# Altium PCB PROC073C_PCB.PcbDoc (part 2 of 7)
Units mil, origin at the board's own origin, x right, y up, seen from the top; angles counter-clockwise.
Board outline 2165.35 x 2695.12 mil, 8 copper layers (Top Layer, L2_GND, L3_SIGNAL 1, L4_SIGNAL 2, L5_SIGNAL 3, L6_SIGNAL 4, L7_GND, Bottom Layer), stack 55.9 mil thick; 393 components, 319 nets, 1311 pads, 1643 vias.
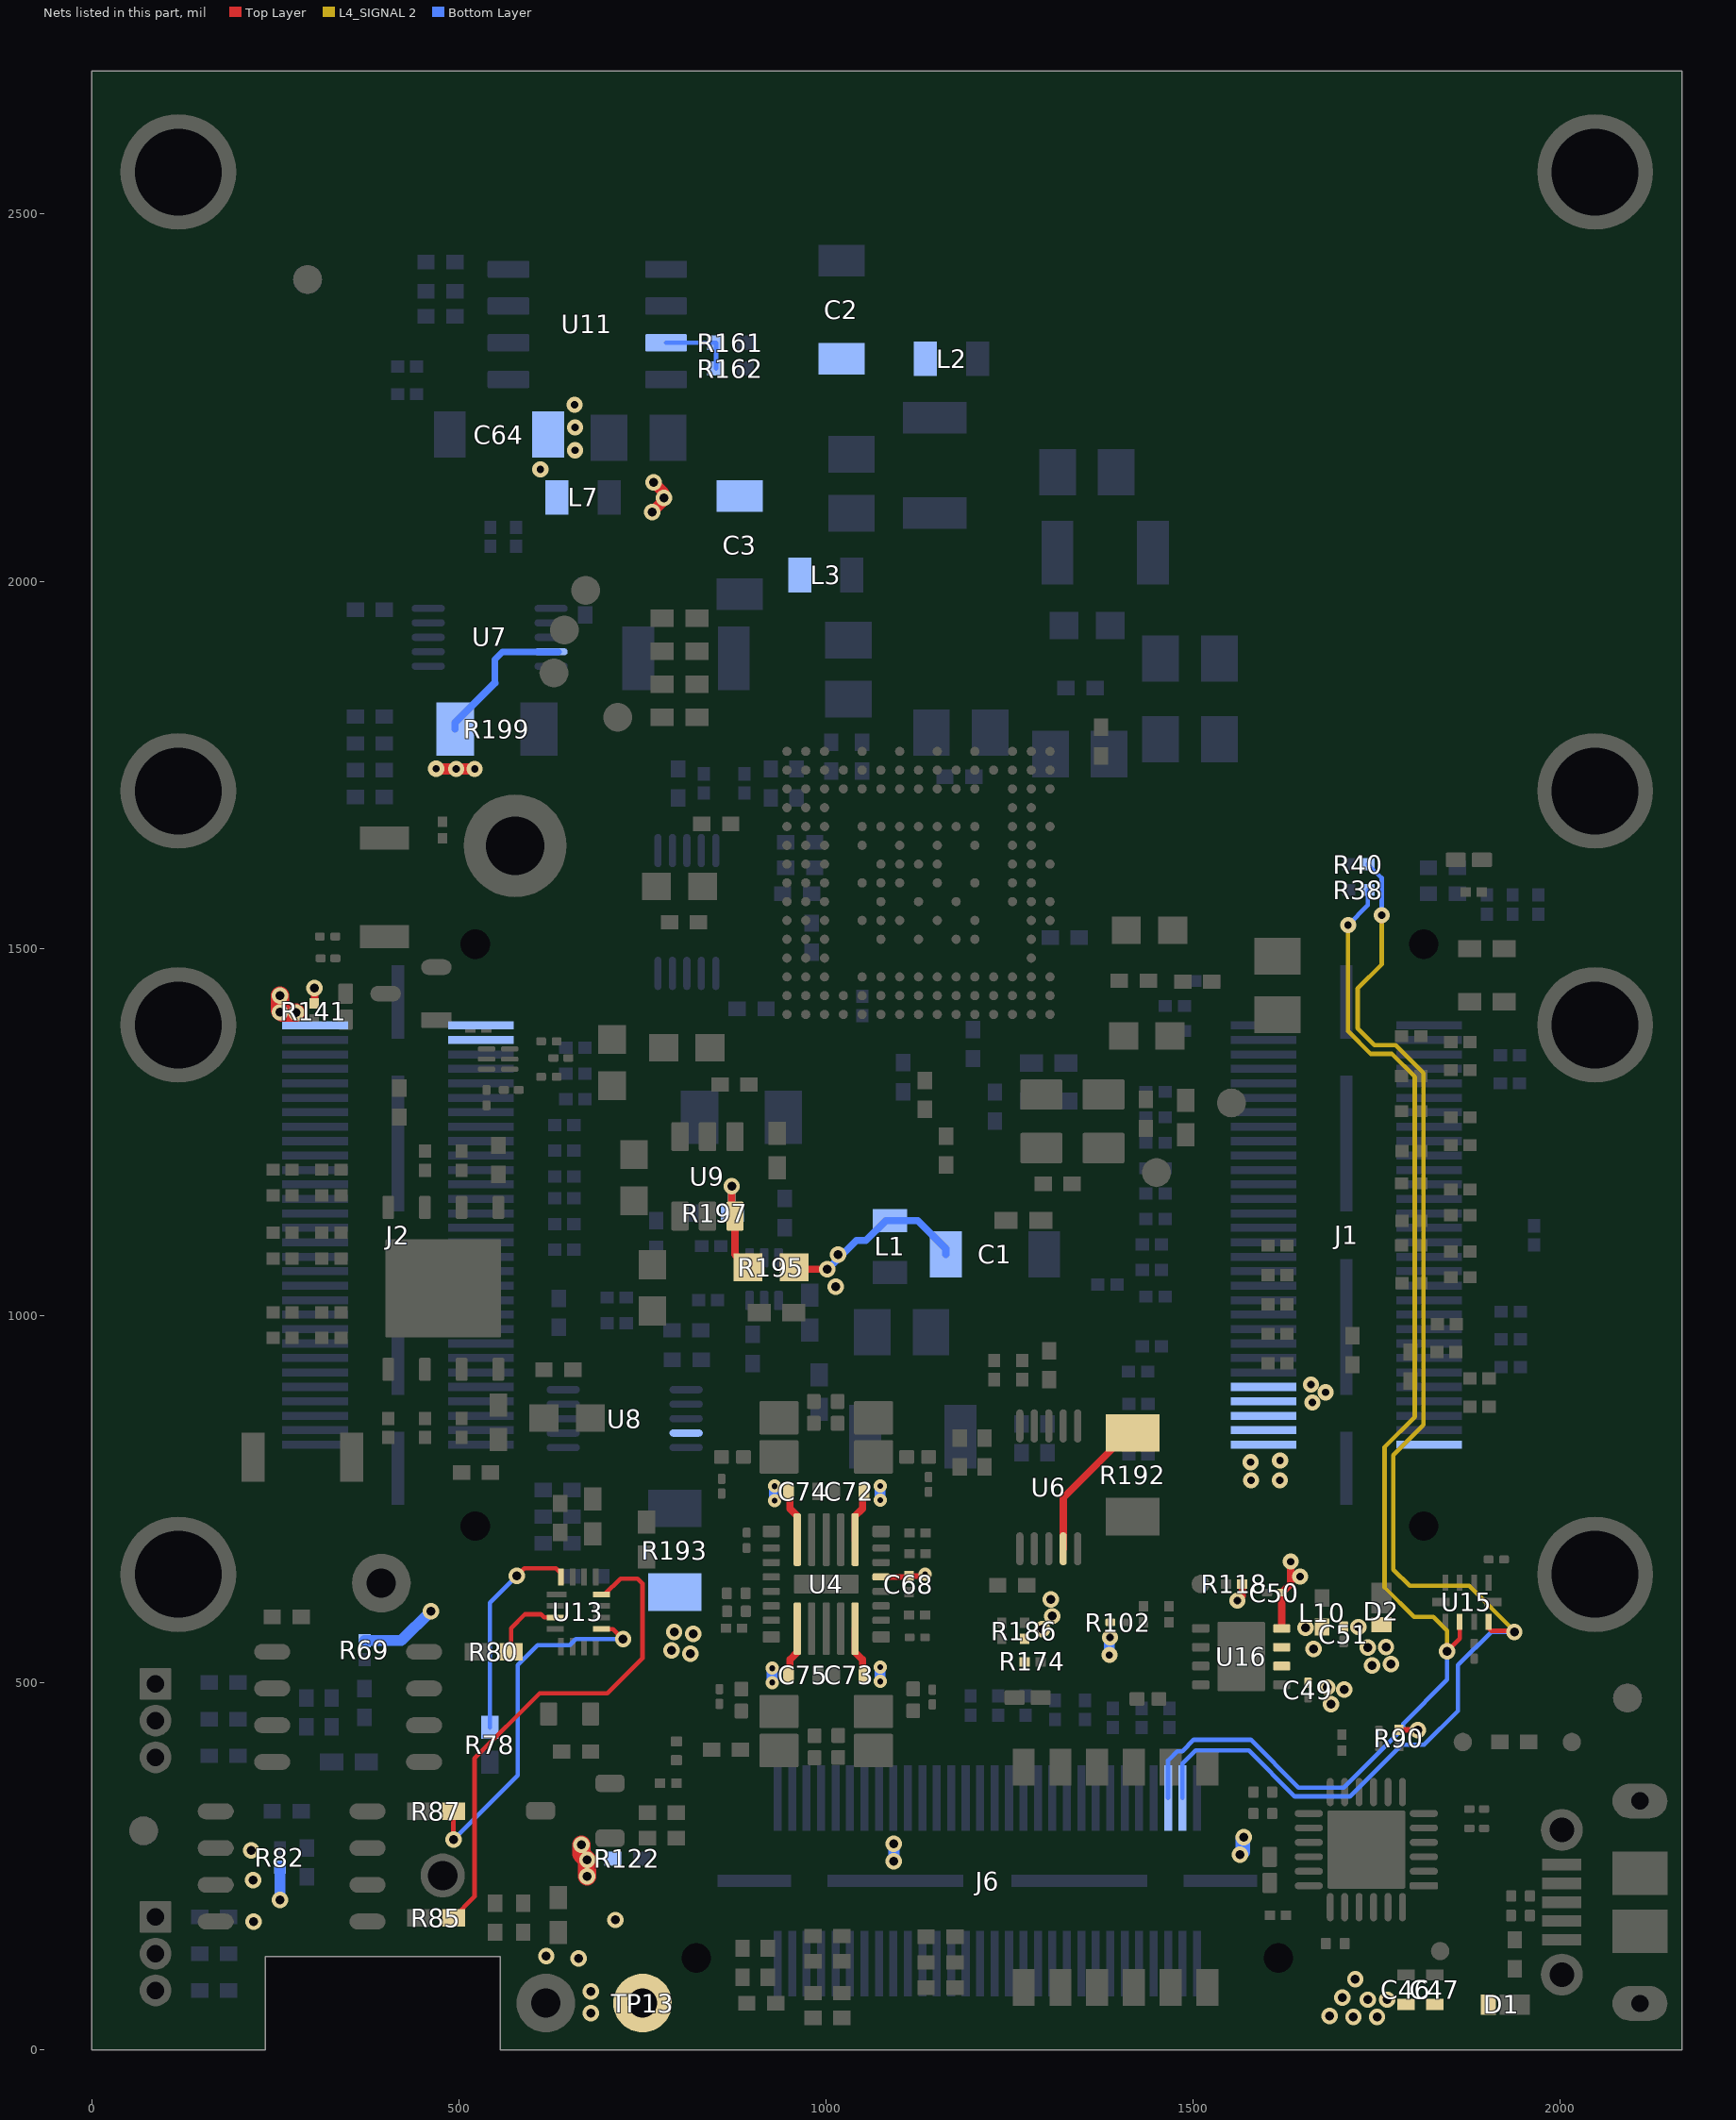
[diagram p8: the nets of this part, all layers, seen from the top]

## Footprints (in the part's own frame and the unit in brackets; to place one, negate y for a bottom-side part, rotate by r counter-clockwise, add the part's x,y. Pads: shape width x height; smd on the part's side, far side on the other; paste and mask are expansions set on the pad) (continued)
CONN_105017-0001 [mm] "Molex Micro USB-B"
  rect 0.4x1.35 smd: 1(-1.3,1.35) 2(-0.65,1.35) 3(0,1.35) 4(0.65,1.35) 5(1.3,1.35)
  oval 1.2x1.9 hole 0.6 slot 1.3 at 90 deg: 6(-3.5,-1.35) 9(3.5,-1.35)
  rect 1.5x1.9 smd: 7(-1,-1.35) 8(1,-1.35)
  round 1.45 hole 0.85: 10(2.5,1.35) 11(-2.5,1.35)
  Top Layer region: 3.5,-0.4 2.3,-0.4 2.3,-2.3 3.5,-2.3
  Top Layer region: -3.5,-2.3 -2.3,-2.3 -2.3,-0.4 -3.5,-0.4
  silkscreen extent -4.1,-0.2 4.1,1.4, body extent -4.1,-3.93 4.1,1.5, height 2.72
D0008A_L [mm] "SOIC, 8-Leads, Body 4.9x3.9mm, Pitch 1.27mm, IPC High Density"
  oval 1.25x0.55 smd: 1(-2.625,1.905) 2(-2.625,0.635) 3(-2.625,-0.635) 4(-2.625,-1.905) 5(2.625,-1.905) 6(2.625,-0.635) 7(2.625,0.635) 8(2.625,1.905)
  silkscreen extent -3.1,-2.5 0.9,2.5, body extent -3,-2.45 3,2.45, height 1.63
DBV0006A_N [mm] "SOT23, 6-Leads, Body 2.9x1.6mm, Pitch 0.95mm, Lead Span 2.8mm, IPC Medium Density"
  rrect17% 1x0.6 smd: 1(-1.375,0.95) 2(-1.375,0) 3(-1.375,-0.95) 4(1.375,-0.95) 5(1.375,0) 6(1.375,0.95)
  silkscreen extent -1.68,-1.55 0.5,1.55, body extent -1.42,-1.46 1.42,1.46, height 1.12
DGS0010A_L [mm] "TSSOP, 10-Leads, Body 3x3mm, Pitch 0.5mm, IPC High Density"
  oval 1.15x0.25 smd: 1(-2.125,1) 2(-2.125,0.5) 3(-2.125,0) 4(-2.125,-0.5) 5(-2.125,-1) 6(2.125,-1) 7(2.125,-0.5) 8(2.125,0) 9(2.125,0.5) 10(2.125,1)
  silkscreen extent -2.65,-1.55 0.9,1.55, body extent -2.45,-1.5 2.45,1.5, height 0.96
DRB0008B [mm] "SON, 8-Leads, Body 3x3mm, Pitch 0.65mm, Thermal Pad 2.4x1.65mm, TI Recommended"
  rrect33% 0.6x0.3 smd: 1(-1.4,0.975) 2(-1.4,0.325) 3(-1.4,-0.325) 4(-1.4,-0.975) 5(1.4,-0.975) 6(1.4,-0.325) 7(1.4,0.325) 8(1.4,0.975)
  rrect9% 1.47x1.06 on Top Paste: 9(0,-0.63) 9(0,0.63)
  rrect6% 1.65x2.4 smd paste-1.2: 9(0,0)
  silkscreen extent -1.73,-1.73 1.73,1.73, body extent -1.5,-1.5 1.5,1.5, height 0.96
DRL0006A [mm] "SOTFL, 6-Flat Leads, Body 1.2x1.6x0.6mm, Pitch 0.5mm, TI recommended"
  rrect33% 0.67x0.3 smd: 1(-0.74,0.5) 2(-0.74,0) 3(-0.74,-0.5) 4(0.74,-0.5) 5(0.74,0) 6(0.74,0.5)
  silkscreen extent -0.9,-0.95 0.5,0.95, body extent -0.8,-0.8 0.8,0.8, height 0.61
DSF0006A [mm] "TI recommended land pattern"
  rrect59% 0.6x0.17 smd mask+0.045: 1(-0.4,0.35) 2(-0.4,0) 3(-0.4,-0.35) 4(0.4,-0.35) 5(0.4,0) 6(0.4,0.35)
  silkscreen extent -0.6,-0.63 0.6,0.63, body extent -0.5,-0.5 0.5,0.5, height 0.48
DSN2_0603 [mm] "SMD, 2-Leads, Body 1.6x0.8mm"
  rect 0.52x0.7 smd: 1(-0.64,0)
  rect 1.05x0.7 smd: 2(0.275,0)
  silkscreen extent -1.4,-0.75 0.8,0.75, body extent -0.8,-0.4 0.8,0.4, height 0.31
FCC_disclaimer [mil]
Fiducial10-20 [mm]
  round 1 smd mask+0.5: 1(0,0)
  Top Layer keep-out circle w1.178: c0,0 r0.5
FP-BSS123-7-F_SOT23-IPC_C [mm]
  rrect18% 1.059x0.547 smd paste+0 mask+0: 1(-0.877,0.915)
  rrect100% 1.059x0.547 smd paste+0 mask+0: 2(-0.877,-0.915) 3(0.877,0)
  body extent -1.51,-1.55 1.51,1.55, height 0.25
FP-CL03A105MO3NRNH_0201-IPC_C [mil]
  rrect33% 15.83x11.94 smd paste+0 mask+0: 1(-9.87,0) 2(9.87,0)
  body extent -22,-12 22,12, height 10
"FP-CL05A226MQ5N6J8_0402 (1005 Metric)-IPC_C" [mil]
  rrect21% 20.29x18.6 smd paste+0 mask+0: 1(-14.9,0) 2(14.9,0)
  body extent -20,-10 20,10, height 22
FP-CP2105-F01-GMR_QFN24-EP-IPC_A [mm]
  rrect42% 0.979x0.239 smd paste+0 mask+0: 1(-1.99,1.25)
  rrect100% 0.979x0.239 smd paste+0 mask+0: 2(-1.99,0.75) 3(-1.99,0.25) 4(-1.99,-0.25) 5(-1.99,-0.75) 6(-1.99,-1.25) 13(1.99,-1.25) 14(1.99,-0.75) 15(1.99,-0.25) 16(1.99,0.25) 17(1.99,0.75) 18(1.99,1.25)
  rrect100% 0.239x0.979 smd paste+0 mask+0: 7(-1.25,-1.99) 8(-0.75,-1.99) 9(-0.25,-1.99) 10(0.25,-1.99) 11(0.75,-1.99) 12(1.25,-1.99) 19(1.25,1.99) 20(0.75,1.99) 21(0.25,1.99) 22(-0.25,1.99) 23(-0.75,1.99) 24(-1.25,1.99)
  rrect4% 2.7x2.7 smd paste-1000 mask+0: 25(0,0)
  body extent -2.98,-2.98 2.98,2.98, height 0.25
FP-CRCW0402200RFKEDHP_0402-IPC_C [mil]
  rrect21% 20.29x18.6 smd paste+0 mask+0: 1(-14.9,0) 2(14.9,0)
  body extent -20,-10 20,10, height 16
"FP-GRM033R6YA104KE14D_0201 (0603 Metric)-IPC_C" [mil]
  rrect38% 13.94x10.34 smd paste+0 mask+0: 1(-10.01,0) 2(10.01,0)
  body extent -21,-10 21,10, height 10
FP-M50-3930342_HDR3-MFG [mm]
  rrect9% 1.1x1.1 hole 0.6 paste-1000 mask+0: 1(-1.27,1)
  round 1.1 hole 0.6 paste-1000 mask+0: 2(0,1) 3(1.27,1)
  silkscreen extent -2.97,-0.6 2.15,1.12, body extent -2.25,-4.9 2.25,1.65, height 0.25
"FP-MCKK2012TR47M_0805 (2012 Metric)-IPC_C" [mil]
  rrect9% 45.45x53.39 smd paste+0 mask+0: 1(-26.61,0) 2(26.61,0)
  body extent -53,-32 53,32, height 10
"FP-RC0201JR-070RL_0201 (0603 Metric)-IPC_C" [mil]
  rrect38% 13.94x10.34 smd paste+0 mask+0: 1(-10.01,0) 2(10.01,0)
  body extent -21,-10 21,10, height 10
"FP-RC0201JR-070RL_0201 (0603 Metric)-MFG" [mm]
  rrect29% 0.35x0.4 smd paste+0 mask+0: 1(-0.325,0) 2(0.325,0)
  body extent -0.3,-0.15 0.3,0.15, height 0.26
"FP-RC0402FR-073R83L_0402 (1005 Metric)-IPC_C" [mil]
  rrect21% 20.29x18.6 smd paste+0 mask+0: 1(-14.9,0) 2(14.9,0)
  body extent -29,-15 29,15, height 10
FP-RR0306P-103-D_0201-IPC_C [mil]
  rrect37% 13.31x10.73 smd paste+0 mask+0: 1(-10.52,0) 2(10.52,0)
  body extent -12,-6 12,6, height 10
"FP-TMK063CG391JT-F_0201 (0603 Metric)-IPC_C" [mil]
  rrect38% 13.94x10.34 smd paste+0 mask+0: 1(-10.01,0) 2(10.01,0)
  body extent -21,-10 21,10, height 10
IEC_HotSurface_Small [mil]
  silkscreen extent -107,-93 107,92
Keystone5001 [mil] "For Keystone 500x miniature loop terminals"
  round 80 hole 40: 1(0,0)
  silkscreen extent -52,-52 52,52, body extent -49,-49 49,49, height 182
Kyocera_CX3225SA [mm] "SMD, 4-Leads, Body 3.2x2.5mm"
  rrect10% 1.05x1.45 smd: 1(-0.925,1.075) 2(-0.925,-1.075) 3(0.925,-1.075) 4(0.925,1.075)
  silkscreen extent -1,2.28 -0.87,2.4, body extent -1.3,-1.65 1.3,1.65, height 0.9
Label_650x200 [mil] "Thermal Transfer Label"
  round 1 on Mech13: 0(0,0)
  silkscreen extent -325,-100 325,100, body extent -325,-100 325,100, height 1
MPZ2012 [mm] "TDK"
  rect 0.8x1.2 smd: 1(-0.9,0) 2(0.9,0)
  body extent -1.1,-0.72 1.1,0.72, height 1.05
RNF0026C [mm] "QFN, 26-Leads, Body 4x4.5mm, Pitch 0.5mm"
  rrect25% 0.6x0.4 smd paste-0.3: 1(-1.9,1.825) 8(-1.9,-1.825) 14(1.9,-1.825) 21(1.9,1.825)
  rrect40% 0.6x0.25 smd paste+0: 2(-1.9,1.25) 3(-1.9,0.75) 4(-1.9,0.25) 5(-1.9,-0.25) 6(-1.9,-0.75) 7(-1.9,-1.25) 15(1.9,-1.25) 16(1.9,-0.75) 17(1.9,-0.25) 18(1.9,0.25) 19(1.9,0.75) 20(1.9,1.25)
  rrect40% 0.25x1.82 smd paste-1: 9(-1,-1.54) 10(-0.5,-1.54) 11(0,-1.54) 12(0.5,-1.54) 13(1,-1.54) 22(1,1.54) 23(0.5,1.54) 24(0,1.54) 25(-0.5,1.54) 26(-1,1.54)
  rrect15% 2.24x0.66 smd paste-1: 27(0,0)
  rrect33% 0.6x0.3 on Top Paste: ""(-1.9,-1.775) ""(-1.9,1.775) ""(1.9,-1.775) ""(1.9,1.775)
  rrect33% 0.3x0.825 on Top Paste: ""(-1.575,-2.037) ""(-1.575,2.037) ""(1.575,-2.037) ""(1.575,2.037)
  rrect40% 0.25x0.81 on Top Paste: ""(-1,2.045) ""(-1,-2.045) ""(-1,-1.035) ""(-1,1.035) ""(-0.5,2.045) ""(-0.5,-2.045) ""(-0.5,-1.035) ""(-0.5,1.035) ""(0,1.035) ""(0,-2.045) ""(0,-1.035) ""(0,2.045) ""(0.5,-2.045) ""(0.5,-1.035) ""(0.5,2.045) ""(0.5,1.035) ""(1,-2.045) ""(1,-1.035) ""(1,1.035) ""(1,2.045)
  rrect15% 0.98x0.66 on Top Paste: ""(-0.59,0) ""(0.59,0)
  Top Layer region: -1.775,1.675 -1.775,2.4 -1.771,2.419 -1.76,2.435 -1.744,2.446 -1.725,2.45 -1.725,2.45 -1.475,2.45 -1.456,2.446 -1.44,2.435 -1.429,2.419 -1.425,2.4 -1.425,2.4 -1.425,1.675 -1.429,1.656 -1.44,1.64 -1.456,1.629 -1.475,1.625 -1.475,1.625 -1.725,1.625 -1.744,1.629 -1.76,1.64 -1.771,1.656 -1.775,1.675
  Top Layer region: 1.425,1.675 1.425,2.4 1.429,2.419 1.44,2.435 1.456,2.446 1.475,2.45 1.475,2.45 1.725,2.45 1.744,2.446 1.76,2.435 1.771,2.419 1.775,2.4 1.775,2.4 1.775,1.675 1.771,1.656 1.76,1.64 1.744,1.629 1.725,1.625 1.725,1.625 1.475,1.625 1.456,1.629 1.44,1.64 1.429,1.656 1.425,1.675
  Top Layer region: 1.425,-2.4 1.425,-1.675 1.429,-1.656 1.44,-1.64 1.456,-1.629 1.475,-1.625 1.475,-1.625 1.725,-1.625 1.744,-1.629 1.76,-1.64 1.771,-1.656 1.775,-1.675 1.775,-1.675 1.775,-2.4 1.771,-2.419 1.76,-2.435 1.744,-2.446 1.725,-2.45 1.725,-2.45 1.475,-2.45 1.456,-2.446 1.44,-2.435 1.429,-2.419 1.425,-2.4
  Top Layer region: -1.775,-2.4 -1.775,-1.675 -1.771,-1.656 -1.76,-1.64 -1.744,-1.629 -1.725,-1.625 -1.725,-1.625 -1.475,-1.625 -1.456,-1.629 -1.44,-1.64 -1.429,-1.656 -1.425,-1.675 -1.425,-1.675 -1.425,-2.4 -1.429,-2.419 -1.44,-2.435 -1.456,-2.446 -1.475,-2.45 -1.475,-2.45 -1.725,-2.45 -1.744,-2.446 -1.76,-2.435 -1.771,-2.419 -1.775,-2.4
  silkscreen extent -2.45,-2.7 2.45,2.7, body extent -2,-2.25 2,2.25, height 0.9
RSE0010A [mm] "QFN, 10-Leads, Body 1.5x2mm, Pitch 0.5mm, TI Recommended"
  rect 0.55x0.2 smd: 1(-0.675,0.75) 2(-0.675,0.25) 3(-0.675,-0.25) 4(-0.675,-0.75) 6(0.675,-0.75) 7(0.675,-0.25) 8(0.675,0.25) 9(0.675,0.75)
  rect 0.3x0.6 smd: 5(0,-0.9) 10(0,0.9)
  silkscreen extent -1.07,-1.18 0.78,1.18, body extent -0.77,-1.02 0.78,1.03, height 0.61
RSV0016A [mm] "QFN, 16-Leads, Body 1.8x2.6mm, Pitch 0.4mm, TI Recommended"
  rect 0.7x0.2 smd: 1(-0.75,0.6)
  rect 0.6x0.2 smd: 2(-0.8,0.2) 3(-0.8,-0.2) 4(-0.8,-0.6) 9(0.8,-0.6) 10(0.8,-0.2) 11(0.8,0.2) 12(0.8,0.6)
  rect 0.2x0.6 smd: 5(-0.6,-1.2) 6(-0.2,-1.2) 7(0.2,-1.2) 8(0.6,-1.2) 13(0.6,1.2) 14(0.2,1.2) 15(-0.2,1.2) 16(-0.6,1.2)
  silkscreen extent -1.08,-1.33 1.08,1.45, body extent -0.92,-1.32 0.93,1.33, height 0.56
Samtec_QSH-030-01-X-D-A [mm] "Receptacle, 0.5 mm, 30x2, TH"
  rect 2.27x0.279 smd: 1(-2.865,7.25) 2(2.865,7.25) 3(-2.865,6.75) 4(2.865,6.75) 5(-2.865,6.25) 6(2.865,6.25) 7(-2.865,5.75) 8(2.865,5.75) 9(-2.865,5.25) 10(2.865,5.25) 11(-2.865,4.75) 12(2.865,4.75) 13(-2.865,4.25) 14(2.865,4.25) 15(-2.865,3.75) 16(2.865,3.75) 17(-2.865,3.25) 18(2.865,3.25) 19(-2.865,2.75) 20(2.865,2.75) 21(-2.865,2.25) 22(2.865,2.25) 23(-2.865,1.75) 24(2.865,1.75) 25(-2.865,1.25) 26(2.865,1.25) 27(-2.865,0.75) 28(2.865,0.75) 29(-2.865,0.25) 30(2.865,0.25) 31(-2.865,-0.25) 32(2.865,-0.25) 33(-2.865,-0.75) 34(2.865,-0.75) 35(-2.865,-1.25) 36(2.865,-1.25) 37(-2.865,-1.75) 38(2.865,-1.75) 39(-2.865,-2.25) 40(2.865,-2.25) 41(-2.865,-2.75) 42(2.865,-2.75) 43(-2.865,-3.25) 44(2.865,-3.25) 45(-2.865,-3.75) 46(2.865,-3.75) 47(-2.865,-4.25) 48(2.865,-4.25) 49(-2.865,-4.75) 50(2.865,-4.75) 51(-2.865,-5.25) 52(2.865,-5.25) 53(-2.865,-5.75) 54(2.865,-5.75) 55(-2.865,-6.25) 56(2.865,-6.25) 57(-2.865,-6.75) 58(2.865,-6.75) 59(-2.865,-7.25) 60(2.865,-7.25)
  round 0 hole 1.02 unplated mask+0.127: MH1(2.67,10.065) MH2(2.67,-10.065)
  rect 0.43x2.54 smd: MP1(0,8.065) MP4(0,-8.065)
  rect 0.43x4.7 smd: MP2(0,3.175) MP3(0,-3.175)
  silkscreen extent -3.9,-10.66 3.62,10.66, body extent -3.75,-10.64 3.75,10.67, height 3.25
SOIC-8 [mm] "duplicate of SO-8.  SOIC, 8-Leads, Body 5.0x4.0mm (max), Pitch 1.27mm, IPC Medium Density"
  rrect17% 1.45x0.6 smd: 1(-2.725,1.905) 2(-2.725,0.635) 3(-2.725,-0.635) 4(-2.725,-1.905) 5(2.725,-1.905) 6(2.725,-0.635) 7(2.725,0.635) 8(2.725,1.905)
  silkscreen extent -3.5,-2.5 0.9,2.5, body extent -3,-2.45 3,2.45, height 1.63
SOT-23 [mm] "SOT23, 3-Leads, Body 2.9x1.3mm, Pitch 0.95mm, Lead Span 2.5mm, IPC Medium Density"
  rrect50% 1x0.6 smd: 1(-1.2,0.95) 2(-1.2,-0.95) 3(1.2,0)
  silkscreen extent -1.62,-1.5 0.7,1.5, body extent -1.16,-1.45 1.21,1.45, height 1
SW_218-6LPST [mm] "SMD, 12-Leads, Body 5.8x8.79mm"
  rect 1.27x0.76 smd: 1(-3.81,3.175) 2(-3.81,1.905) 3(-3.81,0.635) 4(-3.81,-0.635) 5(-3.81,-1.905) 6(-3.81,-3.175) 7(3.81,-3.175) 7(3.81,-3.175) 8(3.81,-1.905) 9(3.81,-0.635) 10(3.81,0.635) 11(3.81,1.905) 12(3.81,3.175)
  silkscreen extent -2.9,-4.4 2.9,4.7, body extent -4.22,-4.4 4.22,4.39, height 2.62
SW_B3U-1000P [mm] "OMRON"
  rect 0.8x1.7 smd: 1(-1.7,0) 2(1.7,0)
  silkscreen extent -1.5,-1.25 1.5,1.25, body extent -1.5,-1.25 1.5,1.25, height 1.75
TI_Stacked_Overlay_Small [mil]
  silkscreen extent -418,-78 -237,98
TI_Symbol_Overlay_Small [mil]
  silkscreen extent -90,-88 91,88
TLMx1000_Yellow [mm] "SMD, 2-Leads, Body 1.6x0.8mm"
  rrect17% 0.6x0.8 smd: 1(-0.725,0) 2(0.725,0)
  silkscreen extent -0.98,-0.8 1.6,0.8, body extent -0.85,-0.45 0.85,0.45, height 0.65
TP_25MIL-SMT [mil]
  round 25 smd mask-2.5: 1(0,0)
TP_SM_1MM [mm] "1mm Test Point, SMT"
  round 1 smd paste-0.5: 1(0,0)
TP_VIA_060RND040 [mil] "TP_VIA_060RND040"
  round 60 hole 40: 1(0,0)
WEEE_Minimum [mil] "WEEElie bin"
  silkscreen extent -95,-172 99,104
WSON-8L_6x5MM_EP [mm] "SMD, 8-Leads, Body 6x5mm, Pitch 1.27mm"
  rrect25% 0.8x0.4 smd: 1(-2.8,1.905) 2(-2.8,0.635) 3(-2.8,-0.635) 4(-2.8,-1.905) 5(2.8,-1.905) 6(2.8,-0.635) 7(2.8,0.635) 8(2.8,1.905)
  rrect3% 3.4x4 smd paste-3: 9(0,0)
  rrect7% 1.468x1.698 on Top Paste: ""(-0.834,0.949) ""(-0.834,-0.949) ""(0.834,0.949) ""(0.834,-0.949)
  silkscreen extent -3.2,-2.7 3.2,2.7, body extent -3.05,-2.55 3.05,2.55, height 0.8

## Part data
C1 C2 C3 C64: library part CMP-0008770-2, "CAP, CERM, 22 uF, 6.3 V, +/- 10%, X7R, AEC-Q200 Grade 1, 1206", Cap_Case=1206_180, Manufacturer=TDK, Supplier Part Number 1=445-7884-1-ND, TempCo=X7R, Tolerance_%=10%, Value1="0.001872 ohm", Value2=6.3V, ValueDisplayed=22uF
C4 C5 C6 C9 C10 C11 C12 C14 C16 C19 C20 C21 C28 C29: library part CMP-0078265-1, "CAP, CERM, 0.22 µF, 16 V,+/- 10%, X7R, AEC-Q200 Grade 1, 0402", Cap_Case=0402, Manufacturer=MuRata, Supplier Part Number 1=490-10671-1-ND, TempCo=X7R, Tolerance_%=10%, Value2=16V, ValueDisplayed=0.22µF
C7 C8 C13 C15 C23 C24: library part CMP-0085348-1, "CAP, CERM, 10 µF, 10 V,+/- 20%, X7R, 0805", Cap_Case=0805, Manufacturer=Kemet, TempCo=X7R, Tolerance_%=20%, Value2=10V, ValueDisplayed=10µF
C17 C27: library part CMP-0007134-5, "CAP, CERM, 2.2 uF, 6.3 V, +/- 10%, X7R, AEC-Q200 Grade 1, 0603", Cap_Case=0603, Manufacturer=MuRata, Supplier Part Number 1=490-5316-1-ND, TempCo=X7R, Tolerance_%=10%, Value1=Unknown, Value2=6.3V, ValueDisplayed=2.2uF
C18 C22 C35: library part CMP-0007136-5, "CAP, CERM, 1 uF, 16 V, +/- 10%, X7R, AEC-Q200 Grade 1, 0603", Cap_Case=0603, Manufacturer=MuRata, Supplier Part Number 1=490-5241-6-ND, TempCo=X7R, Tolerance_%=10%, Value1=Unknown, Value2=16V, ValueDisplayed=1uF
C25 C26: library part CMP-0006351-2, "CAP, CERM, 0.1 uF, 16 V, +/- 10%, X7R, 0402", Cap_Case=0402, Manufacturer=MuRata, Supplier Part Number 1=490-4759-2-ND, TempCo=X7R, Tolerance_%=10%, Value1=Unknown, Value2=16V, ValueDisplayed=0.1uF
C30: library part CMP-0006352-2, "CAP, CERM, 0.01 uF, 25 V, +/- 10%, X7R, 0402", Cap_Case=0402, Manufacturer=MuRata, Supplier Part Number 1=490-6043-2-ND, TempCo=X7R, Tolerance_%=10%, Value1=Unknown, Value2=25V, ValueDisplayed=0.01uF
C31: library part CMP-0064969-1, "CAP, CERM, 0.1 uF, 10 V,+/- 10%, X7S, 0201", Cap_Case=0201, Manufacturer=MuRata, Supplier Part Number 1=490-14450-1-ND, TempCo=X7S, Tolerance_%=10%, Value1=Unknown, Value2=10V, ValueDisplayed=0.1uF
C32 C33: library part CMP-0006367-2, "CAP, CERM, 4.7 pF, 50 V, +/- 2%, C0G/NP0, 0402", Cap_Case=0402, Manufacturer=MuRata, Supplier Part Number 1=490-8102-1-ND, TempCo=C0G/NP0, Tolerance_%=2%, Value1=Unknown, Value2=50V, ValueDisplayed=4.7pF
C34 C36 C57 C58 C59 C63 C65: library part CMP-0006325-2, "CAP, CERM, 0.1 uF, 50 V, +/- 10%, X7R, AEC-Q200 Grade 1, 0402", Cap_Case=0402, Manufacturer=TDK, Supplier Part Number 1=445-6899-1-ND, TempCo=X7R, Tolerance_%=10%, Value1="0.039064 ohm", Value2=50V, ValueDisplayed=0.1uF
C37 C38 C40 C41 C43: library part CMP-0078241-1, "CAP, CERM, 0.1 µF, 10 V,+/- 10%, X7R, 0402", Cap_Case=0402, Manufacturer=Kemet, Supplier Part Number 1=399-3520-1-ND, TempCo=X7R, Tolerance_%=10%, Value2=10V, ValueDisplayed=0.1µF
C39 C42: library part CMP-0006361-2, "CAP, CERM, 4700 pF, 50 V, +/- 10%, X7R, AEC-Q200 Grade 1, 0402", Cap_Case=0402, Manufacturer=MuRata, Supplier Part Number 1=490-4915-1-ND, TempCo=X7R, Tolerance_%=10%, Value1=Unknown, Value2=50V, ValueDisplayed=4700pF
C44 C45 C48 C49 C50 C52 C53: library part CMP-0086440-1, "Cap Ceramic 0.1uF 35V X5R 10% Pad SMD 0201 85C T/R", Manufacturer="Murata Electronics North America", TempCo=15%, Tolerance_%=10%
C46 C47 C72 C73 C74 C75: library part CMP-0006339-4, "CAP, CERM, 10 uF, 10 V, +/- 20%, X5R, 0402", Cap_Case=0402, Manufacturer="Samsung Electro-Mechanics", TempCo=X5R, Tolerance_%=20%, Value1=Unknown, Value2=10V, ValueDisplayed=10uF
C51: library part CMP-0086446-1, "1µF ±20% 16V Ceramic Capacitor X5R 0201", Manufacturer="Samsung Electro-Mechanics", TempCo=15%, Tolerance_%=20%
C54 C55 C56 C60: library part CMP-0086438-1, "CAP CER 390PF 25V C0G/NP0 0201", Manufacturer="Taiyo Yuden", TempCo=30ppm/°C, Tolerance_%=5%
C61 C62 C66 C67: library part CMP-0086447-1, "CAP CER 22UF 6.3V X5R 0402", Manufacturer="Samsung Electro-Mechanics", TempCo=15%, Tolerance_%=20%
C68: library part CMP-0009781-1, "CAP, CERM, 0.22 uF, 10 V, +/- 20%, X5R, 0201", Cap_Case=0201, Manufacturer="Taiyo Yuden", Supplier Part Number 1=587-2483-1-ND, TempCo=X5R, Tolerance_%=20%, Value1=Unknown, Value2=10V, ValueDisplayed=0.22uF
C69: library part CMP-0007111-4, "CAP, CERM, 1 uF, 6.3 V, +/- 10%, X7R, 0603", Cap_Case=0603, Manufacturer="Samsung Electro-Mechanics", TempCo=X7R, Tolerance_%=10%, Value1=Unknown, Value2=6.3V, ValueDisplayed=1uF
C70: library part CMP-0006858-4, "CAP, CERM, 0.1 uF, 50 V, +/- 5%, X7R, 0603", Cap_Case=0603, Manufacturer=Kemet, Supplier Part Number 1=399-7844-1-ND, TempCo=X7R, Tolerance_%=5%, Value1=Unknown, Value2=50V, ValueDisplayed=0.1uF
C71: library part CMP-0006332-2, "CAP, CERM, 1000 pF, 100 V, +/- 10%, X7S, AEC-Q200 Grade 1, 0402", Cap_Case=0402, Manufacturer=TDK, Supplier Part Number 1=445-6904-1-ND, TempCo=X7S, Tolerance_%=10%, Value1="2.71151 ohm", Value2=100V, ValueDisplayed=1000pF
C76 C78 C80 C82: library part CMP-0009174-2, "CAP, CERM, 22 uF, 16 V, +/- 10%, X7R, 1210", Cap_Case=1210, Manufacturer=MuRata, Supplier Part Number 1=490-5242-1-ND, TempCo=X7R, Tolerance_%=10%, Value1=Unknown, Value2=16V, ValueDisplayed=22uF
C77 C79 C81 C83: library part CMP-0008017-2, "CAP, CERM, 10 uF, 10 V, +/- 10%, X7R, 0805", Cap_Case=0805, Manufacturer=MuRata, Supplier Part Number 1=490-10674-1-ND, TempCo=X7R, Tolerance_%=10%, Value1=Unknown, Value2=10V, ValueDisplayed=10uF
"CAUTION HOT SURFACE1": library part CMP-0074837-1, "IEC 61010-1 Hot Surface Warning"
D1 D2: library part CMP-0028829-2, "Diode, Schottky, 30 V, 2 A, 2-XFDFN", Manufacturer="ON Semiconductor", Value1=2A, Value2=0.48V
D3: library part CMP-0078196-2, "LED, Yellow, SMD", Color=yellow, Manufacturer=Vishay-Semiconductor, Power_TotalModule=40mW, Value1=.04W, Value2=1.8V
D4 D5 D6 D7: library part CMP-0067682-2, "LED, Green, SMD", Color=Green, Manufacturer=Kingbright, Power_TotalModule=75mW, Value1=0.075W, Value2=2.1V
FID1 FID2 FID3 FID4 FID5 FID6: library part CMP-0077181-1, "Fiducial mark.  There is nothing to buy or mount.", Manufacturer=N/A
J1 J2 J6: library part CMP-0075524-1, "Receptacle, 0.5 mm, 30x2, Gold, TH", Color=Black, Manufacturer=Samtec, Supplier Part Number 1=SAM8180-ND
J3 J4: library part CMP-0087785-1, "CONN HEADER R/A 3POS 1.27MM", Current_A=1A, Manufacturer=Harwin
J5: library part CMP-0055293-1, "Connector, Receptacle, Micro-USB Type B, R/A, Bottom Mount SMT", Manufacturer=Molex, Supplier Part Number 1=WM1399CT-ND
L1 L2 L3 L7: library part CMP-0003427-2, "Ferrite Bead, 100 ohm @ 100 MHz, 4 A, 0805", Manufacturer=TDK, Value1="0.02 ohm", Value2=4A, ValueDisplayed="100 ohm"
L4 L5 L6 L8: library part CMP-0087178-1, "FIXED IND 470NH 4.5A 39 MOHM SMD", Manufacturer="Taiyo Yuden"
L9 L10 L11 L12: library part CMP-0078934-1, "Inductor, Ferrite Bead, Ferrite, 2.2 A, 0.035 ohm, AEC-Q200 Grade 1, SMD", Manufacturer=MuRata, Supplier Part Number 1=490-16506-1-ND, Value1="0.035 ohm", Value2=2.2A
LBL1: library part CMP-0003625-1, "Thermal Transfer Printable Labels, 0.650\" W x 0.200\" H - 10,000 per roll", Manufacturer=Brady, Supplier Part Number 1=97C5133
Logo1 Logo5: library part CMP-0074838-1, "Texas Instrument Corporate Signature"
Logo2: library part CMP-0074844-1
LOGO3: library part CMP-0074847-1, "FCC_disclaimer"
Logo4: library part CMP-0074769-1
Q1: library part CMP-0087176-1, "MOSFET N-CH 100V 170MA SOT23-3", Manufacturer="Diodes Incorporated"
Q2: library part CMP-0000947-2, "MOSFET, N-CH, 100 V, 0.17 A, SOT-23", Alternate Manufacturer=None, Manufacturer="Fairchild Semiconductor", Supplier Part Number 1=BSS123NCT-ND, Value1=1, Value2="1.8 nC"
R1 R195: library part CMP-0025884-3, "RES, 0, 5%, 0.125 W, 0603", Manufacturer=Vishay/Beyschlag, Power_W=125mW, Supplier Part Number 1=MCT0603-0.0-ZZCT-ND, TempCo=ppm/C, Tolerance_%=5%, Value2=0.125W, Value_Code=0000, ValueDisplayed=0
R2 R14 R44 R49 R52 R53 R54 R70 R71 R83 R84 R88 R94 R101 R103 R104 R105 R106 R107 R112 R113 R114 R115 R116 R117 R139 R142 R145 R146 R147 R152 R157 R158 R161 R162 R203 R206 R209: library part CMP-0025958-3, "RES, 10.0 k, 1%, 0.063 W, AEC-Q200 Grade 0, 0402", Manufacturer=Vishay-Dale, Power_W=63mW, Supplier Part Number 1=541-10.0KLCT-ND, TempCo="100 ppm/C", Tolerance_%=1%, Value2=0.063W, Value_Code=10k0, ValueDisplayed=10.0k
R3 R43 R72 R73 R74 R75 R76 R77 R78 R80 R85 R87 R122 R202 R216: library part CMP-0026992-3, "RES, 0, 5%, 0.1 W, AEC-Q200 Grade 0, 0402", Manufacturer=Panasonic, Power_W=100mW, Supplier Part Number 1=P0.0JCT-ND, TempCo="600 ppm/C", Tolerance_%=5%, Value2=0.1W, Value_Code=0000, ValueDisplayed=0
R4 R5 R6 R7 R8 R9 R10 R11 R12 R13 R16 R22 R24 R25 R29 R30 R31 R32 R33 R34 R35 R36 R37 R38 R39 R40 R41 R42 R55 R56 R58 R59 R60 R61 R62 R63 R64 R65 R66 R67 R69 R82 R108 R109 R110 R111 R131 R133 R134 R135 R136 R137 R140 R143 R144 R159 R160 R217 R218 R219 R220 R221 R222 R223 R224 R225 R226 R227 R228 R229 R230: library part CMP-0027008-4, "RES, 0, 5%, 0.05 W, 0201", Manufacturer=Vishay-Dale, Power_W=50mW, Supplier Part Number 1=72M6743, TempCo=ppm/C, Tolerance_%=5%, Value2=0.05W, Value_Code=0000, ValueDisplayed=0
R15 R17 R18 R19 R20 R21 R23 R26 R27 R28 R124 R125 R126 R127 R128 R129 R130 R132 R148 R149 R163 R164 R166 R167 R168 R170: library part CMP-0078192-2, "RES, 20.0, 1%, 0.05 W, 0201", Manufacturer=Vishay-Dale, Power_W=50mW, Supplier Part Number 1=541-2947-1-ND, TempCo="200 ppm/C", Tolerance_%=1%, Value2=0.05W, Value_Code=20R0, ValueDisplayed=20.0
R45 R46 R47 R48 R51: library part CMP-0027275-3, "RES, 33.2, 1%, 0.05 W, 0201", Manufacturer=Vishay-Dale, Power_W=50mW, Supplier Part Number 1=541-33.2ABCT-ND, TempCo="200 ppm/C", Tolerance_%=1%, Value2=0.05W, Value_Code=33R2, ValueDisplayed=33.2
R50: library part CMP-0026395-2, "RES, 47.5 k, 1%, 0.063 W, AEC-Q200 Grade 0, 0402", Manufacturer=Vishay-Dale, Power_W=63mW, Supplier Part Number 1=541-47.5KLCT-ND, TempCo="100 ppm/C", Tolerance_%=1%, Value2=0.063W, Value_Code=47k5, ValueDisplayed=47.5k
R57 R151 R185: library part CMP-0026822-3, "RES, 0, 5%, 0.063 W, AEC-Q200 Grade 0, 0402", Manufacturer=Vishay-Dale, Power_W=63mW, Supplier Part Number 1=541-0.0JCT-ND, TempCo="200 ppm/C", Tolerance_%=5%, Value2=0.063W, Value_Code=0000, ValueDisplayed=0
R68 R79 R81 R86: library part CMP-0026491-2, "RES, 61.9, 1%, 0.063 W, AEC-Q200 Grade 0, 0402", Manufacturer=Vishay-Dale, Power_W=63mW, Supplier Part Number 1=541-61.9LCT-ND, TempCo="100 ppm/C", Tolerance_%=1%, Value2=0.063W, Value_Code=61R9, ValueDisplayed=61.9
R89: library part CMP-0026938-5, "RES, 4.7 k, 5%, 0.063 W, AEC-Q200 Grade 0, 0402", Manufacturer=Vishay-Dale, Power_W=63mW, Supplier Part Number 1=541-4.7KJCT-ND, TempCo="200 ppm/C", Tolerance_%=5%, Value2=0.063W, Value_Code=4k70, ValueDisplayed=4.7k
R90 R93 R176 R177 R187 R188: library part CMP-0027745-1, "RES, 4.99 k, 1%, 0.05 W, 0201", Manufacturer="Yageo America", Power_W=50mW, Supplier Part Number 1=YAG2712CT-ND, TempCo="200 ppm/C", Tolerance_%=1%, Value2=0.05W, Value_Code=4k99, ValueDisplayed=4.99k
R91 R92 R96 R97 R98 R180 R181 R198 R214: library part CMP-0086442-2, "RES SMD 0 OHM JUMPER 1/20W 0201", Manufacturer=Yageo, Power_W=50mW, TempCo=200ppm/°C, Tolerance_%=5%
R95 R100 R102 R123 R138 R165 R189 R190 R215: library part CMP-0088002-1, "10 kOhms ±0.5% 0.05W, 1/20W Chip Resistor 0201 (0603 Metric)  Thin Film", Manufacturer=Susumu, Power_W=50mW, TempCo=25ppm/°C, Tolerance_%=0.5%
R99 R212 R213: library part CMP-0027072-1, "RES, 220, 5%, 0.05 W, 0201", Manufacturer="Yageo America", Power_W=50mW, Supplier Part Number 1=311-220NCT-ND, TempCo="200 ppm/C", Tolerance_%=5%, Value2=0.05W, Value_Code=220R, ValueDisplayed=220
R118 R141 R171 R174: library part CMP-0027137-1, "RES, 510, 5%, 0.05 W, 0201", Manufacturer="Yageo America", Power_W=50mW, Supplier Part Number 1=YAG2907CT-ND, TempCo="200 ppm/C", Tolerance_%=5%, Value2=0.05W, Value_Code=510R, ValueDisplayed=510
R119 R120 R201: library part CMP-0027261-3, "RES, 100 k, 1%, 0.05 W, 0201", Manufacturer=Vishay-Dale, Power_W=50mW, Supplier Part Number 1=541-100KAABCT-ND, TempCo="100 ppm/C", Tolerance_%=1%, Value2=0.05W, Value_Code=100k
R121: library part CMP-0087183-1, "RES SMD 200 OHM 1% 1/5W 0402", Manufacturer="Vishay Dale", Power_W=200mW, TempCo=100ppm/°C, Tolerance_%=1%
R150 R169 R184: library part CMP-0026825-5, "RES, 10 k, 5%, 0.063 W, AEC-Q200 Grade 0, 0402", Manufacturer=Vishay-Dale, Power_W=63mW, Supplier Part Number 1=541-10KJCT-ND, TempCo="200 ppm/C", Tolerance_%=5%, Value2=0.063W, Value_Code=10k0, ValueDisplayed=10k
R153 R154 R155 R156 R182: library part CMP-0025950-3, "RES, 100 k, 1%, 0.063 W, AEC-Q200 Grade 0, 0402", Manufacturer=Vishay-Dale, Power_W=63mW, Supplier Part Number 1=541-100KLCT-ND, TempCo="100 ppm/C", Tolerance_%=1%, Value2=0.063W, Value_Code=100k
R172 R179: library part CMP-0078212-1, "RES, 510, 5%, 0.1 W, AEC-Q200 Grade 0, 0402", Manufacturer=Panasonic, Power_W=100mW, Supplier Part Number 1=P510JCT-ND, TempCo="200 ppm/C", Tolerance_%=5%, Value2=0.1W, Value_Code=510R, ValueDisplayed=510
R173 R175 R178 R183: library part CMP-0086444-2, "RES Thick Film SMD 3.83O 1% 1/16W 0402 200ppm/°C", Manufacturer=Yageo, Power_W=63mW, TempCo=200ppm/°C, Tolerance_%=1%
R186: library part CMP-0027052-1, "RES, 1.0 k, 5%, 0.05 W, 0201", Manufacturer="Yageo America", Power_W=50mW, Supplier Part Number 1=311-1KNCT-ND, TempCo="200 ppm/C", Tolerance_%=5%, Value2=0.05W, Value_Code=1k00, ValueDisplayed=1.0k
R191: library part CMP-0081973-1, "RES, 0, 0%, 0.25 W, AEC-Q200 Grade 0, 0603", Manufacturer=Vishay-Dale, Power_W=250mW, Supplier Part Number 1=541-2779-1-ND, Tolerance_%=0%, Value2=0.25W, Value_Code=0
R192 R193 R199 R200: library part CMP-0081623-1, "RES, 0.002, 1%, 1 W, AEC-Q200 Grade 0, 1206", Manufacturer=Rohm, Power_W=1W, Supplier Part Number 1=RHM.002ALCT-ND, TempCo="100 ppm/C", Tolerance_%=1%, Value_Code=2L000, ValueDisplayed=0.002
R194: library part CMP-0027452-1, "RES, 1.96 k, 1%, 0.05 W, 0201", Manufacturer="Yageo America", Power_W=50mW, Supplier Part Number 1=YAG2494CT-ND, TempCo="200 ppm/C", Tolerance_%=1%, Value2=0.05W, Value_Code=1k96, ValueDisplayed=1.96k
R196: library part CMP-0026944-3, "RES, 510, 5%, 0.063 W, AEC-Q200 Grade 0, 0402", Manufacturer=Vishay-Dale, Power_W=63mW, Supplier Part Number 1=541-510JCT-ND, TempCo="200 ppm/C", Tolerance_%=5%, Value2=0.063W, Value_Code=510R, ValueDisplayed=510
R197: library part CMP-0026659-1, "RES, 100 k, 1%, 0.1 W, 0402", Manufacturer=Panasonic, Power_W=100mW, TempCo="100 ppm/C", Tolerance_%=1%, Value2=0.1W, Value_Code=100k
R204 R207 R210: library part CMP-0026557-2, "RES, 7.87 k, 1%, 0.063 W, AEC-Q200 Grade 0, 0402", Manufacturer=Vishay-Dale, Power_W=63mW, Supplier Part Number 1=541-7.87KLCT-ND, TempCo="100 ppm/C", Tolerance_%=1%, Value2=0.063W, Value_Code=7k87, ValueDisplayed=7.87k
R205 R208 R211: library part CMP-0026574-2, "RES, 82.5 k, 1%, 0.063 W, AEC-Q200 Grade 0, 0402", Manufacturer=Vishay-Dale, Power_W=63mW, Supplier Part Number 1=541-82.5KLCT-ND, TempCo="100 ppm/C", Tolerance_%=1%, Value2=0.063W, Value_Code=82k5, ValueDisplayed=82.5k
S1: library part CMP-0002304-1, "Switch, SPST, Slide, Off-On, 6 Pos, 0.025A, 24V, SMD", CurrentRating_mA=25A, Manufacturer="CTS Electrocomponents", Supplier Part Number 1=CT2186LPST-ND
S2 S3: library part CMP-0002150-2, "SWITCH TACTILE SPST-NO 0.05A 12V", CurrentRating_mA=50A, Manufacturer="Omron Electronic Components", Supplier Part Number 1=SW1020CT-ND
TP1 TP8 TP9 TP10 TP11: library part CMP-0078143-3, "TEST POINT.  No entry in BOM.", Manufacturer=N/A
TP2 TP3 TP4 TP5 TP6 TP7: library part CMP-0003825-1, "1mm Test Point, SMT", Manufacturer=Any
TP12 TP13 TP14: library part CMP-0055138-1, "Test Point, Miniature, Black, TH", Color=Black, Manufacturer=Keystone, Supplier Part Number 1=36-5001-ND
U1: library part CMP-0081105-1, "IWR1843QAGABL, ABL0161B (FCBGA-161)", Alternate Manufacturer="Texas Instruments"
U2: library part CMP-0079267-1, "2.3V-3.6V, 16M-BIT [x 1/x 2/x 4] CMOS FLASH Memory, WSON-8", Manufacturer="Macronix International Co., LTD", Supplier Part Number 1=1092-1211-ND
U3: library part CMP-0067398-2, "Automotive Grade, 1.4V-Capable +/-0.5degC Temperature Sensor with Alert Function and I2C/SMBus, DRL0006A (SOT-OTHER-6)", Alternate Manufacturer="Texas Instruments"
U4: library part CMP-0079120-2, "4-A + 2.5-A + Two 1.5-A Buck Converters With Integrated Switches, RNF0026C (VQFN-HR-26)", Alternate Manufacturer="Texas Instruments", Alternate PartNumber=LP87524JRNFTQ1
U5 U12: library part CMP-0075992-1, "Automotive Fault Protected CAN Transceiver With Flexible Data-Rate, D0008A (SOIC-8)", Alternate Manufacturer="Texas Instruments", Alternate PartNumber=TCAN1042HGVDRQ1
U6 U7 U8 U10: library part CMP-0037978-1, "High-Side Measurement, Bi-Directional Current / Power Monitor with I2C Interface, 2.7 to 5.5 V, -40 to 125 degC, 10-pin SOP (DGS10), Green (RoHS & no Sb/Br)", Quiescent Current (+/-)(Typ)(mA)=0.33, Rating=Catalog
U9: library part CMP-0077265-1, "5.5-V, 2-A, 80 mohm Low Leakage Load Switch with RCB and Programmable Rise Time, DBV0006A (SOT-23-6)", Alternate Manufacturer="Texas Instruments", Alternate PartNumber=TPS22917DBVT
U11: library part CMP-0005309-2, "IC, EEPROM, 8KBIT, 400KHZ, 8SOIC", Manufacturer="ON Semiconductor", Supplier Part Number 1=CAT24C08WI-GT3CT-ND
U13: library part CMP-0067415-1, "10-Ohm Quad SPDT Analog Switch, RSV0016A (UQFN-16)", Alternate Manufacturer="Texas Instruments"
U14: library part CMP-0087172-1, "I/O Controller Interface IC USB to Dual UART bridge", Manufacturer="Silicon Labs"
U15: library part CMP-0074545-1, "Dual 10-ohm SPDT Analog Switch, RSE0010A (UQFN-10)", Alternate Manufacturer="Texas Instruments"
U16: library part CMP-0043358-3, "Dual In / Single Out Autoswitching Power Mux, 2.8 to 5.5 V, -40 to 85 degC, 8-pin SON (DRB), Green (RoHS & no Sb/Br)", IN1, IN2 Input Voltage(Max)(V)=5.5, IN1, IN2 Input Voltage(Min)(V)=2.8, IN1 Output Current(Max)(A)=1.25, Manufacturer="Texas Instruments"
U17: library part CMP-0051215-4, "Single 3-Input Positive-AND Gate, DSF0006A, LARGE T&R", F @ Nom Voltage(Max)(Mhz)=150, Generic Part Number=SN74LVC1G11, ICC @ Nom Voltage(Max)(mA)=0.01, Manufacturer="Texas Instruments", Operating Temperature Range(C)="-40 to 125,-40 to 85", Rating=Catalog, tpd @ Nom Voltage(Max)(ns)=20,7.8,6.2,4.6, Voltage(Nom)(V)=1.8,2.5,3.3,5
Y1: library part CMP-0004694-3, "Crystal, 40 MHz, 8pF, SMD", Frequency_Fixed=40MHz, Frequency Stability=+/-200ppm, Manufacturer=Kyocera, Supplier Part Number 1=581-CX3225SA40D0PTWC
ZZ1: library part CMP-0003616-3
ZZ2: library part CMP-0077236-1
ZZ3: library part CMP-0077237-1
ZZ4 ZZ5: library part CMP-0077238-1

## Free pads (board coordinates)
  round 157.48 hole 118.11: TH1(118.11,2557.33) TH2(118.11,1714.58) TH3(118.11,1395.91) TH4(118.11,647.88) TH5(2047.24,647.88) TH6(2047.24,1395.91) TH7(2047.24,1714.58) TH8(2047.24,2557.33)
  round 140 hole 80: TH9(576.76,1639.96)

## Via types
v1: diameter 13.77/15.74 (per signal layer), hole 5.9, Top Layer to L2_GND, tented both sides, 894 vias
v2: diameter 22.4, hole 12.2, Top Layer to Bottom Layer, tented both sides, 510 vias
v3: diameter 18, hole 8, Top Layer to Bottom Layer, tented both sides, 74 vias
v4: diameter 13.78/15.75 (per signal layer), hole 5.9, Top Layer to L2_GND, tented both sides, 72 vias
v5: diameter 22, hole 10, Top Layer to Bottom Layer, tented both sides, 61 vias
v6: diameter 19.68, hole 7.87, Top Layer to Bottom Layer, 16 vias
v7: diameter 13.77/15.74 (per signal layer), hole 5.9, Top Layer to L2_GND, tented top, 14 vias
v8: diameter 20, hole 10, Top Layer to Bottom Layer, tented both sides, 1 vias
v9: diameter 13.78/15.75 (per signal layer), hole 5.9, Top Layer to L2_GND, tented top, 1 vias

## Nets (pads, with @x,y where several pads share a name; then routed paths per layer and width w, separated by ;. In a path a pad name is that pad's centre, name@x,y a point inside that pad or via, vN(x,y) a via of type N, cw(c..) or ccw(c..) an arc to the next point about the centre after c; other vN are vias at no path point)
5V_IN: C68.1 C72.1 C73.1 C74.1 C75.1 D2.1 R69.2 R82.2 R90.1 R141.1 R174.1 R186.2 U4.9 U4.13 U4.18 U4.22 U4.26 | length 612.3
  Top Layer w7.87: R90.1@1780.23,436 v2(1806.07,436)
  Top Layer w8: U4.18@1075.13,644.32 1111.76,644.32 C68.1@1112.94,645.5 1132.44,645.5 v3(1134.94,648)
  Top Layer w9.84: R141.1@302.97,1425.21 303.7,1425.95 v2(303.7,1446.25)
  Top Layer w10: C75.1@950.83,509.23 950.83,531.64 960.96,541.77 U4.9@960.96,573.85 ; C74.1@950.83,759.73 950.83,737.32 960.96,727.19 U4.26@960.96,695.11 ; U4.13@1039.7,573.85 1039.7,541.77 1049.83,531.64 C73.1@1049.83,510.63 ; U4.22@1039.7,695.11 1039.7,727.19 1049.83,737.32 C72.1@1049.83,759.73 ; D2.1@1756.62,579.5 D2.1@1756.89,579.22
  Bottom Layer w15: v2(256.48,204.55) R82.2@256.48,249.15 ; R69.2@371.69,557.65 421.8,557.65 v2(462.02,597.88) ; v3(926.91,500.56) v3(926.91,520.05) ; v3(930.04,748.38) v3(930.04,767.88) ; v3(1073.76,748.85) v3(1073.76,768.34) ; v3(1073.78,502.01) v3(1073.78,521.51)
  other v2: 679.79,50.23 679.82,80.01 662.96,125.15 619.12,127.89 220.63,174.93 713.35,177.24 219.85,231.37 217.28,272.11 1743.3,523.8 1769.35,525.83 1737.62,548.12 1762.55,549.06 1294.35,573.01 1308.29,590.91 1305.88,613.81
5V_IN_SW: C51.1 L10.1 R118.1 U16.7 | length 25.6
  Top Layer w10: v5(1560.32,612.12) 1560.71,612.12 1566.81,618.22 R118.1@1566.81,634.76
  other v2: 1663.7,546.47 1653.21,574.91 1724.82,576.15
5V_IN_USB: C46.2 C47.1 C49.1 D1.1 U16.6
  other v2: 1718.17,45.01 1750.34,45.47 1685.95,46.78 1737.99,68.7 1764,68.7 1703.04,71.54 1720.73,96.49 1687.77,471.34 1705.7,490.92 1682.36,493.91
A2: R161.1 R162.2 U11.3 | length 103
  Bottom Layer w6: U11.3@782.28,2324.77 R161.1@850.32,2324.77 R162.2@850.31,2289.77
CAN1_RX: R80.1 U13.3 | length 101.9
  Top Layer w6: R80.1@571.12,542.41 571.12,574.38 590.27,593.53 611.78,593.53 616.23,589.07 U13.3@631.29,589.07
CAN1_TX: R78.1 U13.16 | length 293.8
  Top Layer w6: v2(579,645.82) 589.12,655.94 632.4,655.94 639.17,649.17 U13.16@639.17,644.19
  Bottom Layer w6: R78.1@542.39,439.33 542.39,609.21 v2(579,645.82)
CAN2_RX: R87.1 U13.9 | length 506.3
  Top Layer w6: v2(492.68,286.47) R87.1@492.68,325.13 ; U13.9@694.28,573.33 710.16,573.33 v2(723.85,559.64)
  Bottom Layer w6: v2(492.68,286.47) 580.32,374.11 580.32,524.44 607.09,551.21 650.88,551.21 659.31,559.64 v2(723.85,559.64)
CAN2_TX: R85.1 U13.12 | length 683.4
  Top Layer w6: R85.1@492.68,180.13 521.45,208.9 521.45,397.25 610.17,485.97 702.45,485.97 750.12,533.64 750.12,635.25 743.29,642.08 720.28,642.08 698.77,620.57 U13.12@694.28,620.57
CB_PMIC_1V0: C2.2 C3.2 J1.1 J1.3 L2.1 L3.1 R199.2 U7.9 | length 313.4
  Top Layer w15: v5@469.21,1744.62 v5(496.61,1744.62) v5@521.72,1744.62 ; v2(763.36,2094.51) 779.37,2110.53 v2(779.37,2113.76) 779.37,2120.38 v2(765.2,2134.55)
  Bottom Layer w9: 549.11,1861.53 549.11,1893.78 559.39,1904.05 U7.9@635.73,1904.05
  Bottom Layer w10: R199.2@494.99,1798.74 494.99,1807.41 549.11,1861.53
  other v5: 1578.65,775.81 1617.93,775.93 1578.32,800.67 1618.28,802.87 469.21,1744.78 521.72,1744.62
CB_PMIC_1V2: C64.2 J1.5 J1.7 L7.1 R193.2 U8.9
  other v2: 815.5,539.92 789.54,544.31 819.27,566.78 793.26,569.32
  other v5: 611.1,2152.44 658.36,2178.4 658.35,2209.65 657.55,2240.37
CB_PMIC_1V8: C1.2 J1.9 L1.1 R192.2 R195.1 U6.9 | length 459.7
  Top Layer w10: R195.1@956.75,1065.92 960.23,1062.44 961.14,1063.36 v2(1001.51,1063.36) ; U6.9@1323.04,682.61 1323.04,751.88 1411.63,840.47 R192.2@1417.66,840.47
  Bottom Layer w10: v2(1001.51,1063.36) 1002.3,1063.36 1041.38,1102.44 1054.4,1102.44 1081.55,1129.59 L1.1@1087.23,1129.59 1124.85,1129.59 1163.22,1091.22 C1.2@1163.22,1083.72
  other v2: 1013.46,1039.78 1016.58,1083.45
  other v5: 1662.27,882.01 1680.41,895.76 1660.54,906.14
CONN_5V: C50.1 J1.2 J2.58 J2.59 J2.60 R102.1 R122.1 TP13.1 U16.8 | length 261.6
  Top Layer w10: U16.8@1620.56,574.26 C50.1@1620.56,622.77 1632.9,635.11 v5(1632.9,665.21)
  Top Layer w25: v2(256.29,1435.93) 256.29,1415.66 259.45,1412.5 v2(278.68,1412.5) ; v2(666.75,279.69) 666.75,267.23 v2(675,258.98) 676.89,257.09 674.57,254.77 v2(674.57,236.68)
  Bottom Layer w15: v2@1092.45,257.11 v2(1092.45,280.85) ; v5(1385.91,538.02) v5@1385.91,561.95
  Bottom Layer w20: v2(1563.64,266.36) 1567.5,270.21 1567.5,288.51 v2(1568.93,289.94)
  other v2: 1091.96,257.11 256.29,1413.11
  other v5: 1386.72,561.95 1645.49,644.91
CONN_RS232RX: J6.55 R38.1 U15.7 | length 1790.6
  Top Layer w6: v2(1845.83,543.12) 1862.92,560.21 U15.7@1862.92,583.41
  L4_SIGNAL 2 w6: v5(1710.89,1531.87) 1710.89,1387.43 1741.74,1356.58 1770.68,1356.58 1801.76,1325.5 1801.76,862.45 1760.57,821.26 1760.57,630.1 1800.88,589.78 1827.25,589.78 1845.83,571.2 v2(1845.83,543.12)
  Bottom Layer w6: J6.55@1465.8,343.28 1465.8,394.32 1478.49,407.01 1485.21,407.01 1500.84,422.64 1578.23,422.64 1643.44,357.43 1704.87,357.43 1785.87,438.43 1785.87,444.37 1845.83,504.33 v2(1845.83,543.12) ; v5(1710.89,1531.87) 1737.99,1558.97 R38.1@1737.99,1579.77
CONN_RS232TX: J6.57 R40.1 U15.9 | length 1961.3
  Top Layer w6: U15.9@1902.29,583.41 1902.29,574.97 1906.32,570.94 1937.23,570.94 v2(1937.23,569.58)
  L4_SIGNAL 2 w6: v5(1756.72,1545.42) 1756.72,1478.23 1723.92,1445.43 1723.92,1391.37 1746.71,1368.58 1775.65,1368.58 1813.76,1330.47 1813.76,851.6 1772.57,810.41 1772.57,654.42 1794.82,632.17 1876,632.17 1937.23,570.94 v2(1937.23,569.58)
  Bottom Layer w6: J6.57@1485.49,343.28 1485.49,390.31 1503.17,408 1575.9,408 1638.46,345.43 1713.57,345.43 1783.95,415.8 1814.44,415.8 1860.43,461.79 1860.43,524.14 1905.87,569.58 v2(1937.23,569.58) ; R40.1@1737.99,1614.77 1756.72,1596.05 v5(1756.72,1545.42)
EN_3V3: R195.2 R197.2 U9.3 | length 157
  Top Layer w10: v2(871.6,1176.58) 871.6,1140.18 U9.3@876.14,1135.64 876.14,1083.53 R195.2@893.75,1065.92
  Bottom Layer w10: v2(871.6,1176.58) 871.6,1140.53 R197.2@872.36,1139.77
